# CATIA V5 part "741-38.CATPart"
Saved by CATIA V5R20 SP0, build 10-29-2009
Part number: 741-38
Bounding box of the stored display mesh (mm): x -33 to 33, y -32.999 to 32.999, z -37 to 45
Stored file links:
  C:\Users\Utente\Desktop\IO LAVORO\3D X SITO CF\X SITO\741\741-38.CATPart
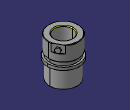
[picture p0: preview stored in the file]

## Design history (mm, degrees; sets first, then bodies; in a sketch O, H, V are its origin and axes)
Set1
  DatumSurface1 to DatumSurface42 "741-38"
Body1 (main body)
